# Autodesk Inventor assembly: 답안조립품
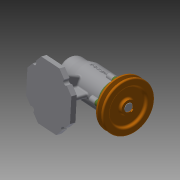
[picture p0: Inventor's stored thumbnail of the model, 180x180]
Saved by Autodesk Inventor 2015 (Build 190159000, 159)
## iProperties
Created: 2019-12
Part Number: 답안조립품
Document SubType Name: Assembly
Designer: now
Author: now
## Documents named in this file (12)
- C:\Users\now\Desktop\491204V1050\답안조립품.iam
- C:\Users\now\Desktop\491204V1050\커버.ipt
- C:\Users\now\Desktop\491204V1050\축.ipt
- C:\Users\now\Desktop\491204V1050\오일 실.ipt
- C:\Users\now\Desktop\491204V1050\어댑터슬리브.ipt
- C:\Users\now\Desktop\491204V1050\볼트 M4.ipt
- C:\Users\now\Desktop\491204V1050\본체.ipt
- C:\Users\now\Desktop\491204V1050\베어링 51202.ipt
- C:\Users\now\Desktop\491204V1050\베어링 6004.ipt
- C:\Users\now\Desktop\491204V1050\멈춤나사 M3.ipt
- C:\Users\now\Desktop\491204V1050\V벨트풀리.ipt
- C:\Users\now\Desktop\491204V1050\Ű 5 x 5 x 16.ipt
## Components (2 placed, 2 different names)
1. V벨트풀리:1 — 플러쉬:1
2. Ű 5 x 5 x 16:1 — 각도:1
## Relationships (2: Angle 1, Flush 1)
- 각도:1 [Angle]: Ű 5 x 5 x 16:1
- 플러쉬:1 [Flush]: V벨트풀리:1
